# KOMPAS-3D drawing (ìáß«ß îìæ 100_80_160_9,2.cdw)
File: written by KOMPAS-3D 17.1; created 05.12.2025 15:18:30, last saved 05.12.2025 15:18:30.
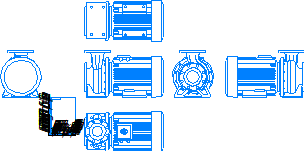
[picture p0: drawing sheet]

Sheet 1: A4, portrait

Title block, sheet 1: name: Насос МНС / 100_80_160_9,2; material: Сталь 10  ГОСТ 1050-88; mass: 257,72; sheets: 1; sheet format: A4

Views: Вид 1, Спереди, Проекционный вид 2, Проекционный вид 3, Проекционный вид 4, Проекционный вид 6
Referenced files in \\adlc.lan\data\АДЛ_ПКД\3D-модели\ADL production\Насосы ГРАНПАМП\Насосы ГРАНПАМП серии МНС\KOMPAS 3D\: Насос МНС 100-80-160_9,2.m3d
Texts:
  Andrey
  АДЛ
Dimensions and other numbers on the sheet: 1:1; 1; 100_80_160_9,2; 257,72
